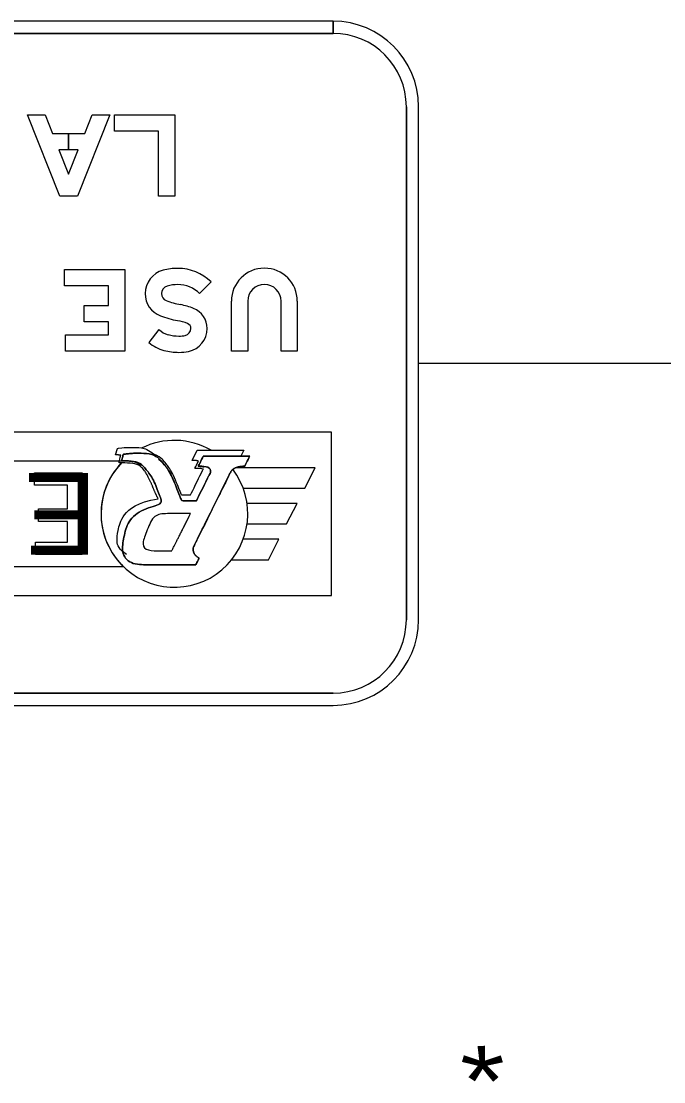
# Model space of a CAD drawing. Extents: x -102643 to -98250, y 54554 to 62384.
# Drawn here: x -101282.4 to -100991.5, y 60711.7 to 61191.3 of the extents above; entities that cross this region are included whole.
import ezdxf

# ---------------------------------------------------------------- set-up
doc = ezdxf.new("R2010")
doc.units = 0
for name, color, linetype in [('LeaderLine_dp', 7, 'Continuous'), ('SignPanel', 7, 'Continuous'), ('TextLabel', 7, 'Continuous')]:
    doc.layers.add(name, color=color, linetype=linetype)

msp = doc.modelspace()

# ---------------------------------------------------------------- linework, layer by layer
at = {"layer": 'LeaderLine_dp'}
msp.add_line((-101102.52, 61036.59), (-100939.46, 61036.59), dxfattribs=at)
at = {"layer": 'SignPanel'}
for p, q in [((-101141.2, 61191.28), (-101461.62, 61191.28)), ((-101141.2, 61191.28), (-101461.62, 61191.28)), ((-101141.25, 61191.28), (-101461.62, 61191.28)), ((-101141.25, 61191.28), (-101461.62, 61191.28)), ((-101141.25, 61185.76), (-101141.25, 61191.28)), ((-101141.25, 61185.76), (-101141.25, 61191.28)), ((-101141.2, 61191.28), (-101141.2, 61185.76)), ((-101141.2, 61191.28), (-101141.2, 61185.76)), ((-101141.2, 61185.76), (-101461.62, 61185.76)), ((-101461.62, 61185.76), (-101141.25, 61185.76)), ((-101461.62, 61185.76), (-101141.25, 61185.76)), ((-101108.05, 60920.58), (-101108.05, 61152.61)), ((-101108.05, 61152.61), (-101108.05, 60920.58)), ((-101108.05, 61152.61), (-101108.05, 60920.58)), ((-101102.52, 60920.58), (-101102.52, 61152.61)), ((-101102.52, 60920.58), (-101102.52, 61152.61)), ((-101102.52, 60920.58), (-101102.52, 61152.61)), ((-101102.52, 60920.58), (-101102.52, 61152.61)), ((-101141.92, 61005.44), (-101460.9, 61005.44)), ((-101141.92, 60931.63), (-101141.92, 61005.44)), ((-101209.87, 60977.12), (-101205.73, 60977.12)), ((-101460.9, 60931.63), (-101141.92, 60931.63)), ((-101461.62, 60887.43), (-101141.2, 60887.43)), ((-101141.2, 60887.43), (-101461.62, 60887.43)), ((-101141.2, 60887.43), (-101461.62, 60887.43)), ((-101461.62, 60881.91), (-101141.2, 60881.91)), ((-101461.62, 60881.91), (-101141.2, 60881.91)), ((-101461.62, 60881.91), (-101141.2, 60881.91)), ((-101461.62, 60881.91), (-101141.2, 60881.91))]:
    msp.add_line(p, q, dxfattribs=at)
for points in [[(-101268.2, 61140.46), (-101253.59, 61140.46), (-101250.22, 61148.93), (-101242.3, 61148.93), (-101256.93, 61112.1), (-101264.86, 61112.1), (-101279.5, 61148.93), (-101271.57, 61148.93)], [(-101260.9, 61133.09), (-101260.9, 61140.46), (-101253.59, 61140.46), (-101250.22, 61148.93), (-101242.3, 61148.93), (-101256.93, 61112.1), (-101264.86, 61112.1), (-101279.5, 61148.93), (-101271.57, 61148.93), (-101268.2, 61140.46), (-101260.9, 61140.46), (-101260.9, 61133.09), (-101265.28, 61133.09), (-101260.9, 61122.07), (-101256.52, 61133.09)], [(-101260.9, 61133.09), (-101260.9, 61140.46), (-101253.59, 61140.46), (-101250.22, 61148.93), (-101242.3, 61148.93), (-101256.93, 61112.1), (-101264.86, 61112.1), (-101279.5, 61148.93), (-101271.57, 61148.93), (-101268.2, 61140.46), (-101260.9, 61140.46), (-101260.9, 61133.09), (-101265.28, 61133.09), (-101260.9, 61122.07), (-101256.52, 61133.09)], [(-101220.2, 61141.56), (-101240.09, 61141.56), (-101240.09, 61148.93), (-101212.83, 61148.93), (-101212.83, 61112.1), (-101220.2, 61112.1)], [(-101220.2, 61141.56), (-101240.09, 61141.56), (-101240.09, 61148.93), (-101212.83, 61148.93), (-101212.83, 61112.1), (-101220.2, 61112.1)], [(-101220.2, 61141.56), (-101240.09, 61141.56), (-101240.09, 61148.93), (-101212.83, 61148.93), (-101212.83, 61112.1), (-101220.2, 61112.1)], [(-101256.52, 61133.09), (-101265.28, 61133.09), (-101260.9, 61122.07)], [(-101262.37, 61042.12), (-101262.37, 61049.48), (-101242.85, 61049.48), (-101242.85, 61055.38), (-101253.9, 61055.38), (-101253.9, 61062.74), (-101242.85, 61062.74), (-101242.85, 61071.58), (-101262.74, 61071.58), (-101262.74, 61078.95), (-101235.48, 61078.95), (-101235.48, 61042.12)], [(-101262.37, 61042.12), (-101262.37, 61049.48), (-101242.85, 61049.48), (-101242.85, 61055.38), (-101253.9, 61055.38), (-101253.9, 61062.74), (-101242.85, 61062.74), (-101242.85, 61071.58), (-101262.74, 61071.58), (-101262.74, 61078.95), (-101235.48, 61078.95), (-101235.48, 61042.12)], [(-101262.37, 61042.12), (-101262.37, 61049.48), (-101242.85, 61049.48), (-101242.85, 61055.38), (-101253.9, 61055.38), (-101253.9, 61062.74), (-101242.85, 61062.74), (-101242.85, 61071.58), (-101262.74, 61071.58), (-101262.74, 61078.95), (-101235.48, 61078.95), (-101235.48, 61042.12)]]:
    msp.add_lwpolyline(points, close=True, dxfattribs=at)
for points in [[(-101201.63, 61068.13), (-101196.44, 61073.36)], [(-101201.63, 61068.13), (-101196.44, 61073.36)], [(-101201.63, 61068.13), (-101196.44, 61073.36)], [(-101179.87, 61064.68), (-101179.87, 61042.12), (-101187.24, 61042.12), (-101187.24, 61064.68)], [(-101179.87, 61064.68), (-101179.87, 61042.12), (-101187.24, 61042.12), (-101187.24, 61064.68)], [(-101179.87, 61064.68), (-101179.87, 61042.12), (-101187.24, 61042.12), (-101187.24, 61064.68)], [(-101157.4, 61064.68), (-101157.4, 61042.12), (-101164.77, 61042.12), (-101164.77, 61064.68)], [(-101157.4, 61064.68), (-101157.4, 61042.12), (-101164.77, 61042.12), (-101164.77, 61064.68)], [(-101157.4, 61064.68), (-101157.4, 61042.12), (-101164.77, 61042.12), (-101164.77, 61064.68)], [(-101220.02, 61051.84), (-101224.57, 61046.03)], [(-101220.02, 61051.84), (-101224.57, 61046.03)], [(-101220.02, 61051.84), (-101224.57, 61046.03)], [(-101239.69, 60995.14), (-101238.85, 60998.09), (-101238.27, 60998.17)], [(-101204.96, 60992.68), (-101202.66, 60997.28), (-101181.61, 60997.28), (-101182.95, 60994.61)], [(-101236.01, 60944.54), (-101453.52, 60944.54), (-101429.08, 60992.52), (-101236.01, 60992.52)], [(-101254.75, 60986.98), (-101254.75, 60950.08), (-101275.87, 60950.08), (-101275.87, 60955.73), (-101261.38, 60955.73), (-101261.38, 60965.01), (-101274.48, 60965.01), (-101274.48, 60970.71), (-101261.38, 60970.71), (-101261.38, 60981.47), (-101276.43, 60981.47), (-101276.43, 60986.98), (-101254.75, 60986.98)], [(-101181.89, 60980.07), (-101154, 60980.07), (-101149.3, 60989.3), (-101185.41, 60989.3)], [(-101180.14, 60963.92), (-101162.23, 60963.92), (-101157.53, 60973.15), (-101180.15, 60973.15)], [(-101187.11, 60947.77), (-101170.46, 60947.77), (-101165.76, 60957), (-101181.89, 60957)]]:
    msp.add_lwpolyline(points, dxfattribs=at)
for centre, radius, start, end in [((-101141.2, 61152.61), 38.67, 360, 90), ((-101141.2, 61152.61), 38.67, 360, 90), ((-101141.2, 61152.61), 38.67, 360, 90), ((-101141.2, 61152.61), 38.67, 360, 90), ((-101141.2, 61152.61), 33.15, 360, 90), ((-101141.2, 61152.61), 33.15, 360, 90), ((-101141.2, 61152.61), 33.15, 360, 90), ((-101172.32, 61064.68), 14.92, 360, 180), ((-101172.32, 61064.68), 14.92, 360, 180), ((-101172.32, 61064.68), 14.92, 360, 180), ((-101172.32, 61064.68), 7.55, 360, 180), ((-101172.32, 61064.68), 7.55, 360, 180), ((-101172.32, 61064.68), 7.55, 360, 180), ((-101213.04, 60968.53), 33.21, 59.9567, 116.8991), ((-101213.04, 60968.53), 33.21, 136.1786, 226.2389), ((-101213.04, 60968.53), 33.21, 136.1786, 37.2709), ((-101141.2, 60920.58), 38.67, 270, 360), ((-101141.2, 60920.58), 38.67, 270, 360), ((-101141.2, 60920.58), 33.15, 270, 360), ((-101141.2, 60920.58), 38.67, 270, 360), ((-101141.2, 60920.58), 33.15, 270, 360), ((-101141.2, 60920.58), 38.67, 270, 360), ((-101141.2, 60920.58), 33.15, 270, 360)]:
    msp.add_arc(centre, radius, start, end, dxfattribs=at)
for centre, major_axis, start_param, end_param in [((-101215.33, 61068.08), (0, -10.94), 3.401517, 4.712389), ((-101215.33, 61068.08), (0, -10.94), 3.401517, 4.712389), ((-101215.33, 61068.08), (0, -10.94), 3.401517, 4.712389), ((-101211.44, 61053.43), (0, -26.1), 3.141593, 3.401517), ((-101211.44, 61053.43), (0, -26.1), 3.141593, 3.401517), ((-101211.44, 61053.43), (0, -26.1), 3.141593, 3.401517), ((-101211.44, 61058.23), (0, -21.3), 2.360607, 3.141593), ((-101211.44, 61058.23), (0, -21.3), 2.360607, 3.141593), ((-101211.44, 61058.23), (0, -21.3), 2.360607, 3.141593), ((-101215.55, 61068.08), (0, -10.73), 4.712389, 5.918637), ((-101215.55, 61068.08), (0, -10.73), 4.712389, 5.918637), ((-101215.55, 61068.08), (0, -10.73), 4.712389, 5.918637), ((-101215.33, 61068.08), (0, -3.58), 3.401517, 4.712389), ((-101215.33, 61068.08), (0, -3.58), 3.401517, 4.712389), ((-101215.33, 61068.08), (0, -3.58), 3.401517, 4.712389), ((-101215.55, 61068.08), (0, -3.36), 4.712389, 5.918637), ((-101215.55, 61068.08), (0, -3.36), 4.712389, 5.918637), ((-101215.55, 61068.08), (0, -3.36), 4.712389, 5.918637), ((-101211.44, 61053.43), (0, -18.73), 3.141593, 3.401517), ((-101211.44, 61053.43), (0, -18.73), 3.141593, 3.401517), ((-101211.44, 61053.43), (0, -18.73), 3.141593, 3.401517), ((-101211.44, 61058.23), (0, -13.93), 2.360607, 3.141593), ((-101211.44, 61058.23), (0, -13.93), 2.360607, 3.141593), ((-101211.44, 61058.23), (0, -13.93), 2.360607, 3.141593), ((-101203.39, 61099.95), (0, -37.47), 5.918637, 6.099033), ((-101203.39, 61099.95), (0, -37.47), 5.918637, 6.099033), ((-101203.39, 61099.95), (0, -37.47), 5.918637, 6.099033), ((-101216, 61032.24), (0, -31.4), 2.761249, 2.95744), ((-101216, 61032.24), (0, -31.4), 2.761249, 2.95744), ((-101216, 61032.24), (0, -31.4), 2.761249, 2.95744), ((-101207.97, 61052.32), (0, -9.77), 1.570796, 2.761249), ((-101207.97, 61052.32), (0, -9.77), 1.570796, 2.761249), ((-101207.97, 61052.32), (0, -9.77), 1.570796, 2.761249), ((-101203.39, 61099.95), (0, -44.84), 5.918637, 6.099033), ((-101203.39, 61099.95), (0, -44.84), 5.918637, 6.099033), ((-101203.39, 61099.95), (0, -44.84), 5.918637, 6.099033), ((-101216, 61032.24), (0, -24.03), 2.761249, 2.95744), ((-101216, 61032.24), (0, -24.03), 2.761249, 2.95744), ((-101216, 61032.24), (0, -24.03), 2.761249, 2.95744), ((-101207.97, 61052.32), (0, -2.41), 1.570796, 2.761249), ((-101207.97, 61052.32), (0, -2.41), 1.570796, 2.761249), ((-101207.97, 61052.32), (0, -2.41), 1.570796, 2.761249), ((-101213.46, 61058.75), (0, -9.53), 5.523837, 6.026234), ((-101213.46, 61058.75), (0, -9.53), 5.523837, 6.026234), ((-101213.46, 61058.75), (0, -9.53), 5.523837, 6.026234), ((-101210.99, 61068.15), (0, -19.24), 6.026234, 6.283185), ((-101210.99, 61068.15), (0, -19.24), 6.026234, 6.283185), ((-101210.99, 61068.15), (0, -19.24), 6.026234, 6.283185), ((-101210.99, 61063.24), (0, -14.33), 0, 0.202758), ((-101210.99, 61063.24), (0, -14.33), 0, 0.202758), ((-101210.99, 61063.24), (0, -14.33), 0, 0.202758), ((-101208.75, 61052.32), (0, -3.18), 0.202758, 1.570796), ((-101208.75, 61052.32), (0, -3.18), 0.202758, 1.570796), ((-101208.75, 61052.32), (0, -3.18), 0.202758, 1.570796), ((-101208.75, 61052.32), (0, -10.55), 0.202758, 1.570796), ((-101208.75, 61052.32), (0, -10.55), 0.202758, 1.570796), ((-101208.75, 61052.32), (0, -10.55), 0.202758, 1.570796), ((-101213.46, 61058.75), (0, -16.89), 5.565152, 6.026234), ((-101213.46, 61058.75), (0, -16.89), 5.565152, 6.026234), ((-101213.46, 61058.75), (0, -16.89), 5.565152, 6.026234), ((-101210.99, 61068.15), (0, -26.61), 6.026234, 6.283185), ((-101210.99, 61068.15), (0, -26.61), 6.026234, 6.283185), ((-101210.99, 61068.15), (0, -26.61), 6.026234, 6.283185), ((-101210.99, 61063.24), (0, -21.7), 0, 0.202758), ((-101210.99, 61063.24), (0, -21.7), 0, 0.202758), ((-101210.99, 61063.24), (0, -21.7), 0, 0.202758)]:
    msp.add_ellipse(centre, major_axis=major_axis, ratio=0.999994, start_param=start_param, end_param=end_param, dxfattribs=at)
for points, degree in [([(-101238.27, 60998.17), (-101235.88, 60998.49), (-101234.34, 60998.57), (-101232.57, 60998.57), (-101228.01, 60998.57), (-101224.82, 60997.55), (-101222.33, 60995.47)], 3), ([(-101237.24, 60995.05), (-101238.04, 60995.11), (-101238.87, 60995.14), (-101239.69, 60995.14)], 2), ([(-101225.77, 60986.88), (-101226.06, 60987.3), (-101226.36, 60987.71), (-101226.67, 60988.09), (-101228.9, 60990.87), (-101232.74, 60991.54), (-101238.24, 60991.54), (-101238.24, 60991.54), (-101237.63, 60993.66), (-101237.24, 60995.05)], 3), ([(-101203.05, 60974.45), (-101203.05, 60974.45), (-101197.41, 60985.83), (-101197.41, 60985.83), (-101196.39, 60987.49), (-101197.13, 60990), (-101202.28, 60990), (-101202.28, 60990), (-101199.98, 60994.61), (-101199.98, 60994.61), (-101199.98, 60994.61), (-101178.93, 60994.61), (-101178.93, 60994.61), (-101178.93, 60994.61), (-101181.23, 60990), (-101181.23, 60990), (-101181.23, 60990), (-101181.89, 60990), (-101181.89, 60990), (-101181.89, 60990), (-101182.6, 60989.97), (-101182.6, 60989.97), (-101182.6, 60989.97), (-101183.19, 60989.91), (-101183.19, 60989.91), (-101183.19, 60989.91), (-101184.22, 60989.69), (-101184.22, 60989.69), (-101184.22, 60989.69), (-101185, 60989.48), (-101185, 60989.48), (-101185, 60989.48), (-101185.65, 60989.2), (-101185.65, 60989.2), (-101185.65, 60989.2), (-101186.12, 60988.95), (-101186.12, 60988.95), (-101186.12, 60988.95), (-101186.58, 60988.67), (-101186.58, 60988.67), (-101186.58, 60988.67), (-101187.05, 60988.23), (-101187.05, 60988.23), (-101187.05, 60988.23), (-101187.39, 60987.8), (-101187.39, 60987.8), (-101187.39, 60987.8), (-101187.52, 60987.54), (-101187.52, 60987.54), (-101187.52, 60987.54), (-101204.44, 60953.45), (-101204.44, 60953.45), (-101204.44, 60953.45), (-101204.5, 60952.95), (-101204.5, 60952.95), (-101204.5, 60952.95), (-101204.5, 60952.49), (-101204.5, 60952.49), (-101204.5, 60952.49), (-101204.5, 60952.14), (-101204.5, 60952.14), (-101204.5, 60952.14), (-101204.47, 60951.71), (-101204.47, 60951.71), (-101204.47, 60951.71), (-101204.35, 60951.18), (-101204.35, 60951.18), (-101204.35, 60951.18), (-101204.13, 60950.62), (-101204.13, 60950.62), (-101204.13, 60950.62), (-101203.91, 60950.25), (-101203.91, 60950.25), (-101203.91, 60950.25), (-101203.51, 60949.72), (-101203.51, 60949.72), (-101203.51, 60949.72), (-101202.95, 60949.25), (-101202.95, 60949.25), (-101202.95, 60949.25), (-101202.39, 60948.85), (-101202.39, 60948.85), (-101202.39, 60948.85), (-101201.83, 60948.51), (-101201.83, 60948.51), (-101201.83, 60948.51), (-101203.35, 60945.49), (-101203.35, 60945.49), (-101203.35, 60945.49), (-101224.05, 60945.49), (-101224.05, 60945.49), (-101233.44, 60945.49), (-101237.21, 60951.19), (-101235.89, 60957.85), (-101234.43, 60965.23), (-101227.35, 60971.01), (-101217.71, 60972.7), (-101219.82, 60976.63), (-101222.34, 60984.17), (-101225.95, 60988.67), (-101228.39, 60991.72), (-101232.66, 60992.46), (-101237.02, 60992.46), (-101237.02, 60992.46), (-101236.17, 60995.41), (-101236.17, 60995.41), (-101236.17, 60995.41), (-101235.6, 60995.49), (-101235.6, 60995.49), (-101233.2, 60995.81), (-101231.66, 60995.89), (-101229.9, 60995.89), (-101224.04, 60995.89), (-101220.44, 60994.21), (-101217.67, 60990.76), (-101214.45, 60986.74), (-101211.33, 60978.19), (-101209.78, 60974.45), (-101209.78, 60974.45), (-101203.05, 60974.45), (-101203.05, 60974.45)], 3), ([(-101200.29, 60961.82), (-101202.68, 60957.01), (-101204.44, 60953.45), (-101204.44, 60953.45), (-101204.44, 60953.45), (-101204.5, 60952.95), (-101204.5, 60952.95), (-101204.5, 60952.95), (-101204.5, 60952.49), (-101204.5, 60952.49), (-101204.5, 60952.49), (-101204.5, 60952.14), (-101204.5, 60952.14), (-101204.5, 60952.14), (-101204.47, 60951.71), (-101204.47, 60951.71), (-101204.47, 60951.71), (-101204.35, 60951.18), (-101204.35, 60951.18), (-101204.35, 60951.18), (-101204.13, 60950.62), (-101204.13, 60950.62), (-101204.13, 60950.62), (-101203.91, 60950.25), (-101203.91, 60950.25), (-101203.91, 60950.25), (-101203.51, 60949.72), (-101203.51, 60949.72), (-101203.51, 60949.72), (-101202.95, 60949.25), (-101202.95, 60949.25), (-101202.95, 60949.25), (-101202.39, 60948.85), (-101202.39, 60948.85), (-101202.39, 60948.85), (-101201.83, 60948.51), (-101201.83, 60948.51), (-101201.83, 60948.51), (-101203.35, 60945.49), (-101203.35, 60945.49), (-101203.35, 60945.49), (-101224.05, 60945.49), (-101224.05, 60945.49), (-101233.44, 60945.49), (-101237.21, 60951.19), (-101235.89, 60957.85), (-101234.43, 60965.23), (-101227.35, 60971.01), (-101217.71, 60972.7), (-101219.82, 60976.63), (-101222.34, 60984.17), (-101225.95, 60988.67), (-101228.39, 60991.72), (-101232.66, 60992.46), (-101237.02, 60992.46), (-101237.02, 60992.46), (-101236.17, 60995.41), (-101236.17, 60995.41), (-101236.17, 60995.41), (-101235.6, 60995.49), (-101235.6, 60995.49), (-101233.2, 60995.81), (-101231.66, 60995.89), (-101229.9, 60995.89), (-101224.04, 60995.89), (-101220.44, 60994.21), (-101217.67, 60990.76), (-101214.45, 60986.74), (-101211.33, 60978.19), (-101209.78, 60974.45), (-101209.78, 60974.45), (-101203.05, 60974.45), (-101203.05, 60974.45)], 3), ([(-101236.3, 60994.96), (-101236.54, 60994.13), (-101237.02, 60992.46), (-101237.02, 60992.46), (-101233.69, 60992.46), (-101230.41, 60992.03), (-101227.95, 60990.46)], 3), ([(-101209.87, 60977.12), (-101211.42, 60981.02), (-101214.13, 60987.82), (-101216.95, 60991.33), (-101218.42, 60993.17), (-101220.17, 60994.55), (-101222.33, 60995.47)], 3), ([(-101220.16, 60993.19), (-101219.25, 60992.51), (-101218.43, 60991.7), (-101217.67, 60990.76), (-101215.08, 60987.53), (-101212.56, 60981.36), (-101210.86, 60977.12)], 3), ([(-101202.14, 60992.34), (-101202.88, 60992.55), (-101203.81, 60992.68), (-101204.96, 60992.68)], 2), ([(-101199.94, 60988.76), (-101200.84, 60988.96), (-101202.09, 60989.08), (-101203.78, 60989.08), (-101203.78, 60989.08), (-101202.96, 60990.72), (-101202.14, 60992.34)], 3), ([(-101203.05, 60974.45), (-101203.05, 60974.45), (-101197.41, 60985.83), (-101197.41, 60985.83), (-101196.39, 60987.49), (-101197.13, 60990), (-101202.28, 60990), (-101202.28, 60990), (-101199.98, 60994.61), (-101199.98, 60994.61), (-101199.98, 60994.61), (-101178.93, 60994.61), (-101178.93, 60994.61), (-101178.93, 60994.61), (-101181.23, 60990), (-101181.23, 60990), (-101181.23, 60990), (-101181.89, 60990), (-101181.89, 60990), (-101181.89, 60990), (-101182.6, 60989.97), (-101182.6, 60989.97), (-101182.6, 60989.97), (-101183.19, 60989.91), (-101183.19, 60989.91), (-101183.19, 60989.91), (-101184.22, 60989.69), (-101184.22, 60989.69), (-101184.22, 60989.69), (-101185, 60989.48), (-101185, 60989.48), (-101185, 60989.48), (-101185.65, 60989.2), (-101185.65, 60989.2), (-101185.65, 60989.2), (-101186.12, 60988.95), (-101186.12, 60988.95), (-101186.12, 60988.95), (-101186.58, 60988.67), (-101186.58, 60988.67), (-101186.58, 60988.67), (-101187.05, 60988.23), (-101187.05, 60988.23), (-101187.05, 60988.23), (-101187.39, 60987.8), (-101187.39, 60987.8), (-101187.39, 60987.8), (-101187.52, 60987.54), (-101187.52, 60987.54), (-101187.52, 60987.54), (-101195.24, 60971.99), (-101200.25, 60961.9)], 3), ([(-101201.28, 60992.02), (-101201.8, 60990.97), (-101202.28, 60990), (-101202.28, 60990), (-101201.25, 60990), (-101200.39, 60989.9), (-101199.69, 60989.73)], 3), ([(-101220.38, 60975.37), (-101221.89, 60978.18), (-101223.61, 60982.84), (-101225.79, 60986.91)], 2), ([(-101205.73, 60977.12), (-101205.73, 60977.12), (-101200.09, 60988.5), (-101200.09, 60988.5), (-101200.03, 60988.59), (-101199.99, 60988.68), (-101199.94, 60988.76)], 3), ([(-101234.73, 60950.18), (-101238.18, 60952.41), (-101239.41, 60956.27), (-101238.57, 60960.52), (-101237.11, 60967.91), (-101230.03, 60973.69), (-101220.38, 60975.37)], 3), ([(-101207.35, 60965.42), (-101206.37, 60967.36), (-101205.69, 60968.7), (-101205.69, 60968.7), (-101205.69, 60968.7), (-101208.5, 60968.7), (-101208.5, 60968.7), (-101217.73, 60968.7), (-101222.71, 60968.02), (-101225.81, 60960), (-101227.96, 60954.43), (-101225.58, 60951.72), (-101218.68, 60951.72), (-101218.68, 60951.72), (-101214.26, 60951.72), (-101214.26, 60951.72)], 3), ([(-101214.26, 60951.72), (-101214.26, 60951.72), (-101209.88, 60960.39), (-101207.38, 60965.34)], 2)]:
    msp.add_open_spline(points, degree=degree, dxfattribs=at)

# ---------------------------------------------------------------- texts
msp.add_text('E', height=36.9, rotation=180, dxfattribs=at).set_placement((-101248.11, 60986.98))
msp.add_text('E', height=36.9, rotation=180, dxfattribs=at).set_placement((-101248.11, 60986.98))
at = {"layer": 'TextLabel'}
msp.add_text('*', height=35, rotation=74.008, dxfattribs=at).set_placement((-101051.33, 60703.72))

doc.saveas('drawing.dxf')
